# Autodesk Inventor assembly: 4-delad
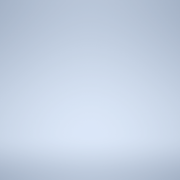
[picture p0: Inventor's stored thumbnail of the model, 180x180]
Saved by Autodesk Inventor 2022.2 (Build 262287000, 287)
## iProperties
RuleStatus: InUse
Created: 2019-06
Part Number: 4-delad
Document SubType Name: Assembly
Designer: cl
Daghöjd: 4000,000 mm
BladBredd: 737,500 mm
Fönsterbredd: 480,000 mm
Fönsterhöjd: 862,000 mm
Brösthöjd: 1070,000 mm
DagBredd: 4500,000 mm
GångjärnsHöjd: 2500,000 mm
AntalBlad: 6,000 ul
Blad2: 762,500 mm
Blad3: 1525,000 mm
Blad4: 1525,000 mm
Blad5: 762,500 mm
Blad6: 2025,000 mm
MGJ2Djup: 0,000 mm
MGJ2Bredd: 5012,500 mm
MGJ12Djup: 0,000 mm
MGJ12Bredd: 0,000 mm
MGJ56Djup: 0,000 mm
MGJ56Bredd: 0,000 mm
MGJ23Djup: 0,000 mm
MGJ23Bredd: 0,000 mm
MGJ45Djup: 0,000 mm
MGJ45Bredd: 0,000 mm
GarageRegel5: 1525,000 mm
GarageRegel6: 1525,000 mm
Author: cl
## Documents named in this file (1)
- G:\AutoCad\Carl Lund\3D-modeller systemlösningar\3D-modell-systemlösning-2022\Styrande(4-Del-0Glas-In).iam
## Named parameters: Fönsterhöjd = 862 mm, Blad2 = 762.5 mm, Blad3 = 1525 mm, Blad4 = 1525 mm, Blad5 = 762.5 mm, Blad6 = 2025 mm, MGJ12Djup = 0, MGJ12Bredd = 0, MGJ2Djup = 0, MGJ2Bredd = 5012.5 mm, MGJ56Djup = 0, MGJ56Bredd = 0, MGJ23Djup = 0, MGJ23Bredd = 0, MGJ45Djup = 0, MGJ45Bredd = 0, GarageRegel5 = 1525 mm, GarageRegel6 = 1525 mm
